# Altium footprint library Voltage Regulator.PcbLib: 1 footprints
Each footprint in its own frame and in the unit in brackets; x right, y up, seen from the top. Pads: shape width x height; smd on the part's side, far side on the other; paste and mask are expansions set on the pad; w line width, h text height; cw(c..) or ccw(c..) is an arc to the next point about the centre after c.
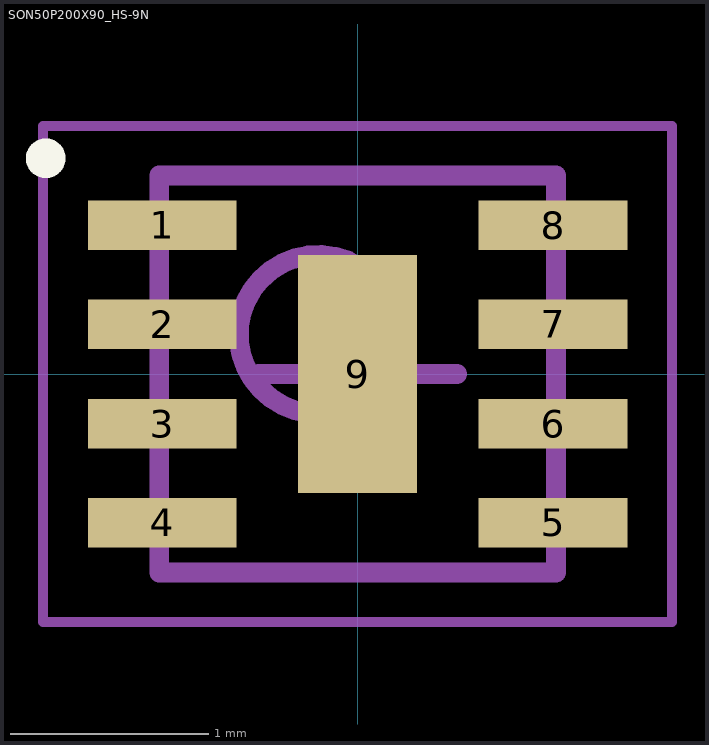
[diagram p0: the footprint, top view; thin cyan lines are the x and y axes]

## SON50P200X90_HS-9N [mm] "SON, 8-Leads, Body 2.00x2.00mm, Pitch 0.50mm, Thermal Pad 1.20x0.60mm, IPC Medium Density"
height 0.9
pads (9):
  rect 0.75x0.25 smd: 1(-0.985,0.75) 2(-0.985,0.25) 3(-0.985,-0.25) 4(-0.985,-0.75) 5(0.985,-0.75) 6(0.985,-0.25) 7(0.985,0.25) 8(0.985,0.75)
  rect 0.6x1.2 smd: 9(0,0)
Top Overlay:
  circle w0.1: c-1.572,1.087 r0.05
Mechanical 13:
  circle w0.1: c-0.2,0.2 r0.4
  lines w0.1: -1,-1 -1,1 1,1 1,-1 -1,-1
Mechanical 15:
  lines w0.05: -1.585,-1.25 -1.585,1.25 1.585,1.25 1.585,-1.25 -1.585,-1.25
  lines w0.1: -0.5,0 0.5,0 ; 0,-0.5 0,0.5
3D body: height 0.9, standoff 0.05, extent -1,-1 1,1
